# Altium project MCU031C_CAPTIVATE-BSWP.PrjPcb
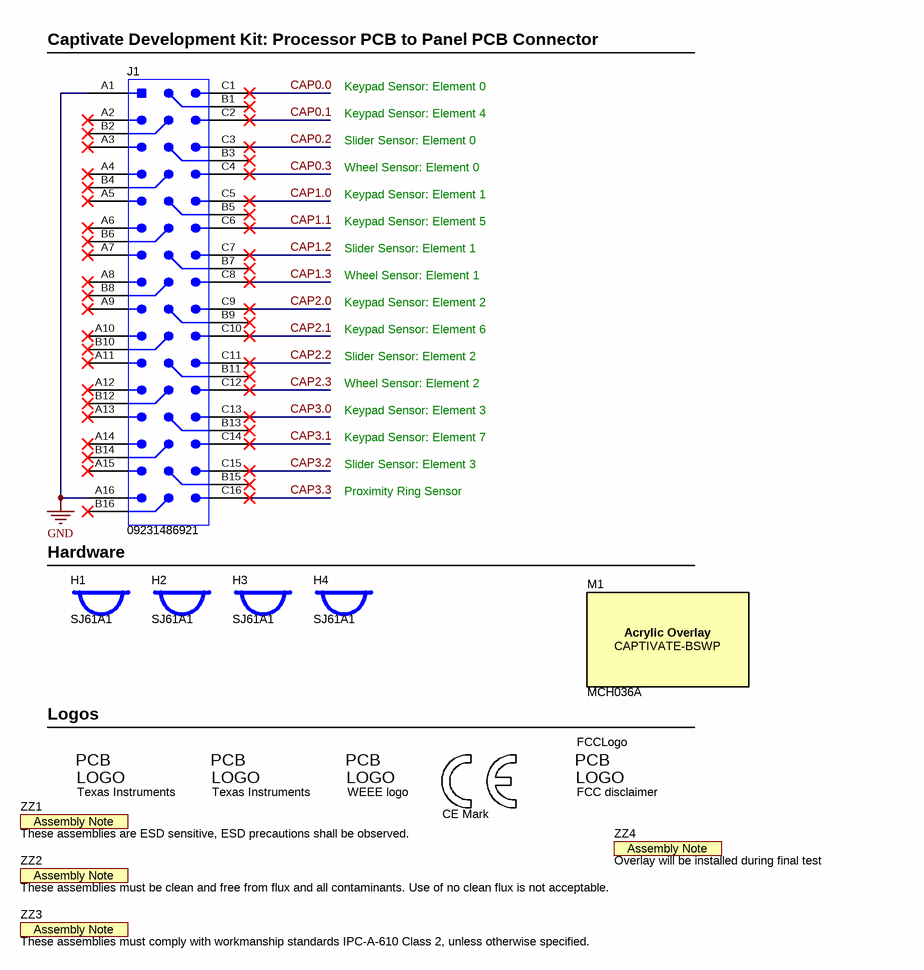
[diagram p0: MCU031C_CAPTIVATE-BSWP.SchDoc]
CopyrightYear: 2015; CountryOfManufacture: U.S.; PCB_Layout: Walter Schnoor; PCB_Rev: C; PRJ_Customer: Public Release; PRJ_Engineer: Walter Schnoor; PRJ_Number: MCU031; PRJ_Title: CAPTIVATE-BSWP; SCH_Rev: C; TechSupport: http://www.ti.com/support; TID: N/A
1 sheet, 15 parts. Net scope: global (net labels, ports and power ports of the same name join across sheets).
Board file: MCU031C_CAPTIVATE-BSWP.PcbDoc

## Sheet MCU031C_CAPTIVATE-BSWP.SchDoc: TICAPEVM_BSWP Capacitive Touch Panel PCB
size Letter; Date: Not shown in title block; ApprovedBy: Not shown in title block; CheckedBy: Not shown in title block; Author: Not shown in title block; CompanyName: Not shown in title block; DrawnBy: W. Schnoor; Engineer: Not shown in title block; Organization: Not shown in title block; Address1: Not shown in title block; Address2: Not shown in title block; Address3: Not shown in title block; Address4: Not shown in title block; DocumentNumber: 1; Revision: Use project parameter SCH_Rev; SheetNumber: 1; SheetTotal: 1; PageSetup: Record=PageOptions¦CenterHorizontal=True¦CenterVertical=True¦PrintScale=1.00¦XCorrection=1.00¦YCorrection=1.00¦PrintKind=0¦BorderSize=5000000¦LeftOffset=0¦BottomOffset=0¦Orientation=2¦PaperLength=1000¦PaperWidth=1000¦Scale=100¦PaperSource=15¦PrintQuality=600¦MediaType=1¦DitherType=10¦PaperKind=Letter¦PrintScaleMode=1

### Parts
CE_Logo  CE Mark  [CE_Mark_5mm]  (no BOM)
FCCLogo  FCC disclaimer  [FCC_disclaimer]  (no BOM)
H1  SJ61A1  [Bumpon_SJ61A1]
H2  SJ61A1  [Bumpon_SJ61A1]
H3  SJ61A1  [Bumpon_SJ61A1]
H4  SJ61A1  [Bumpon_SJ61A1]
J1  09231486921  [Harting_09231486921]
M1  MCH036A  [MCH036]
TI_LOGO_1  Texas Instruments  [TI_Horizontal_Overlay_Medium]  (no BOM)
TI_LOGO_2  Texas Instruments  [TI_Horizontal_Overlay_Medium]  (no BOM)
WEEELogo  WEEE logo  [WEEE_Minimum]  (no BOM)
ZZ1  These assemblies are ESD sensitive, ESD precautions shall be observed.  [AssemblyNote]  (no BOM)
ZZ2  These assemblies must be clean and free from flux and all contaminants. Use of no clean flux is not acceptable.  [AssemblyNote]  (no BOM)
ZZ3  These assemblies must comply with workmanship standards IPC-A-610 Class 2, unless otherwise specified.  [AssemblyNote]  (no BOM)
ZZ4  Overlay will be installed during final test  [AssemblyNote]  (no BOM)

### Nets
GND: J1.A1 J1.A16
CAP0.0: J1.C1
CAP0.1: J1.C2
CAP0.2: J1.C3
CAP0.3: J1.C4
CAP1.0: J1.C5
CAP1.1: J1.C6
CAP1.2: J1.C7
CAP1.3: J1.C8
CAP2.0: J1.C9
CAP2.1: J1.C10
CAP2.2: J1.C11
CAP2.3: J1.C12
CAP3.0: J1.C13
CAP3.1: J1.C14
CAP3.2: J1.C15
CAP3.3: J1.C16

Not connected (* = marked no-connect by the designer): J1 A2* A3* A4* A5* A6* A7* A8* A9* A10* A11* A12* A13* A14* A15* B1* B2* B3* B4* B5* B6* B7* B8* B9* B10* B11* B12* B13* B14* B15* B16*

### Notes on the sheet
- (near J1) Captivate Development Kit: Processor PCB to Panel PCB Connector
- Keypad Sensor: Element 0
- Keypad Sensor: Element 4
- Slider Sensor: Element 0
- Wheel Sensor: Element 0
- Keypad Sensor: Element 1
- Keypad Sensor: Element 5
- Slider Sensor: Element 1
- Wheel Sensor: Element 1
- Keypad Sensor: Element 2
- Keypad Sensor: Element 6
- Slider Sensor: Element 2
- Wheel Sensor: Element 2
- Keypad Sensor: Element 3
- Keypad Sensor: Element 7
- Slider Sensor: Element 3
- Proximity Ring Sensor
- Hardware
- (near TI_LOGO_1) Logos

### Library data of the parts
CE_Logo = CMP-0074844-1: SymbolCreator: a0412235
FCCLogo = CMP-0074847-1: FCC_disclaimer
H1-H4 = SJ61A1: Bumpon, Cylindrical, 0.312 X 0.200, Black; Manufacturer: 3M; SymbolCreator: a0412235
J1 = CMP-0084037-1: Header(shrouded), 2.54mm, 16x3, Gold, R/A, TH; Manufacturer: Harting; Current_A: 2A; Shrouded: Y; Gender: Male; Row_Count: 3; RowSpacing_mm: 2.54
M1 = MCH036: CAPTIVATE-BSWP Overlay; SymbolCreator: a0273983; CompType: Overlay Plastic; U/M: EA, IN, or GM
TI_LOGO_1 TI_LOGO_2 = TI_Logo: Texas Instrument Corporate Signature; SymbolCreator: a0412235
WEEELogo = CMP-0074769-1
ZZ1 = CMP-0077236-1
ZZ2 = CMP-0077237-1
ZZ3 = CMP-0077238-1
ZZ4 = CMP-0003615-1: This Assembly Note will show in the PcbDoc and associated outputs

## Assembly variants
001: all parts fitted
